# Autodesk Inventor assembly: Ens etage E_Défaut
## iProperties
Shininess: 64.0
Length Units: 11269
Angle Units: 11279
Time Units: 11290
Mass Units: 11283
Length Display Precision: 3
Angle Display Precision: 2
Compacted: True
Created: 2006-01
Part Number: Ens etage E_Défaut
Document SubType Name: Assembly
Designer: Fricot
Density: 0.0
Volumn: 0.0
Area: 0.0
PropertySet Name: Model Information
Control State: 0
Master: False
Checked Out: False
Author: Fricot
